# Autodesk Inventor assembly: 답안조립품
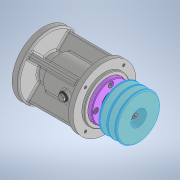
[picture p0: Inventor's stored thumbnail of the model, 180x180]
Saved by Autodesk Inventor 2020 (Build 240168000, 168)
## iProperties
Created: 2024-10
Part Number: 답안조립품
Document SubType Name: Assembly
Designer: oem
Author: oem
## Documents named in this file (18)
- C:\Users\oem\Desktop\741004V1006\답안조립품.iam
- C:\Users\oem\Desktop\741004V1006\본체.ipt
- C:\Users\oem\Desktop\741004V1006\스러스트 볼베어링 512 02.ipt
- C:\Users\oem\Desktop\741004V1006\어뎁터.ipt
- C:\Users\oem\Desktop\741004V1006\육각 소켓 머리 볼트 M5x10.ipt
- C:\Users\oem\Desktop\741004V1006\깊은 홈 볼베어링 6004.ipt
- C:\Users\oem\Desktop\741004V1006\축.ipt
- C:\Users\oem\Desktop\741004V1006\칼라.ipt
- C:\Users\oem\Desktop\741004V1006\커버.ipt
- C:\Users\oem\Desktop\741004V1006\가스켓.ipt
- C:\Users\oem\Desktop\741004V1006\오일 실 20 35 8.ipt
- C:\Users\oem\Desktop\741004V1006\평행키 5x5x22.ipt
- C:\Users\oem\Desktop\741004V1006\V 벨트 풀리.ipt
- C:\Users\oem\Desktop\741004V1006\엔드캡.ipt
- C:\Users\oem\Desktop\741004V1006\스프링와셔 M5.ipt
- C:\Users\oem\Desktop\741004V1006\평와셔 M5.ipt
- C:\Users\oem\Desktop\741004V1006\실링 패드.ipt
- C:\Users\oem\Desktop\741004V1006\육각 머리 볼트 M6x0.75x12.ipt
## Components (2 placed, 2 different names)
1. 가스켓:1
2. V 벨트 풀리:1 — 각도:1
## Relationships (1: Angle 1)
- 각도:1 [Angle]: V 벨트 풀리:1
